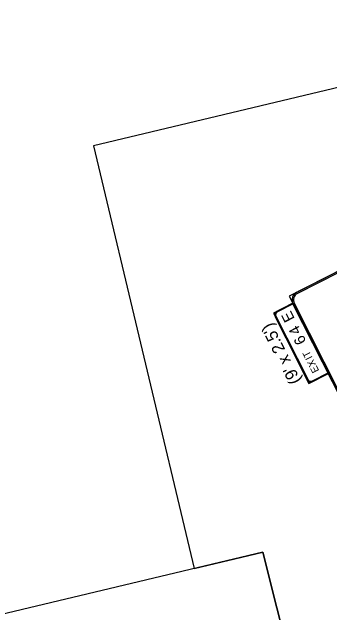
# Model space of a CAD drawing. Extents: x -5665 to 1997148, y 4 to 812485.
# Drawn here: x 1972829 to 1973482, y 805489 to 806723 of the extents above; entities that cross this region are included whole.
import ezdxf

# ---------------------------------------------------------------- set-up
doc = ezdxf.new("R2010")
doc.units = 0
doc.layers.add('RD_EX_H20_TX', color=7, linetype='Continuous')
doc.layers.add('RD_SHT_TX', color=7, linetype='Continuous')

msp = doc.modelspace()

# ---------------------------------------------------------------- linework, layer by layer
at = {"layer": 'RD_EX_H20_TX'}
for points in [[(1973692.8, 804229.2), (1974094.7, 803428), (1974666.8, 802557.5), (1980293.7, 803871.4), (1979319.1, 807956.8), (1972996.5, 806448.5), (1973203.6, 805580.6), (1973344.3, 805614.1)], [(1967695.1, 802969), (1968000.2, 801689.9), (1968522.9, 801587.9), (1968575.1, 801281.2), (1968568.4, 800839.6), (1968542.7, 800594.7), (1968247.7, 800080.4), (1974570.3, 801588.8), (1974094.7, 803428), (1973692.8, 804229.2), (1973344.3, 805614.1), (1967347.3, 804183.5), (1967746.1, 803578.5)]]:
    msp.add_lwpolyline(points, close=True, dxfattribs=at)
at = {"layer": 'RD_SHT_TX'}
for points in [[(1973623.2, 806253.6), (1973398.3, 806139.8), (1973528.3, 805882.8)], [(1973414.4, 806148), (1973623.2, 806253.6)], [(1973624.5, 806250.9), (1973415.7, 806145.3)], [(1973406.3, 806125.1), (1973366.2, 806104.8), (1973439.3, 805960.3), (1973479.4, 805980.6), (1973479.4, 805980.6)], [(1973374.2, 806108.9), (1973406.3, 806125.1)], [(1973407, 806123.8), (1973374.9, 806107.5)], [(1973528.3, 805882.8), (1973406.4, 806123.8)], [(1973409.1, 806125.1), (1973531, 805884.2)], [(1973435.2, 805968.3), (1973370.2, 806096.8)], [(1973371.6, 806097.5), (1973436.6, 805969)], [(1973446.6, 805965.7), (1973478.8, 805981.9)], [(1973479.4, 805980.6), (1973447.3, 805964.3)]]:
    msp.add_lwpolyline(points, dxfattribs=at)
for centre, radius, start, end in [((1973422.5, 806131.9), 18, 116.8317, 206.8319), ((1973422.5, 806131.9), 15, 116.8317, 206.8319), ((1973378.3, 806100.9), 9, 116.8317, 206.8319), ((1973378.3, 806100.9), 7.5, 116.8317, 206.8319), ((1973443.3, 805972.4), 9, 206.8319, 296.8315), ((1973443.3, 805972.4), 7.5, 206.8319, 296.8315)]:
    msp.add_arc(centre, radius, start, end, dxfattribs=at)

# ---------------------------------------------------------------- texts
for s, height, p in [('E', 22.5, (1973410.6, 806093.3)), ("(9' x 2.5')", 25, (1973423.3, 805966.1)), ('4', 22.5, (1973424.1, 806066.8)), ('6', 22.5, (1973434.3, 806046.6)), ('T', 15, (1973444.3, 806018.4)), ('I', 15, (1973446.9, 806013.3)), ('X', 15, (1973454.1, 805999.1)), ('E', 15, (1973460.5, 805986.5))]:
    msp.add_text(s, height=height, rotation=116.8317, dxfattribs=at).set_placement(p)

doc.saveas('drawing.dxf')
